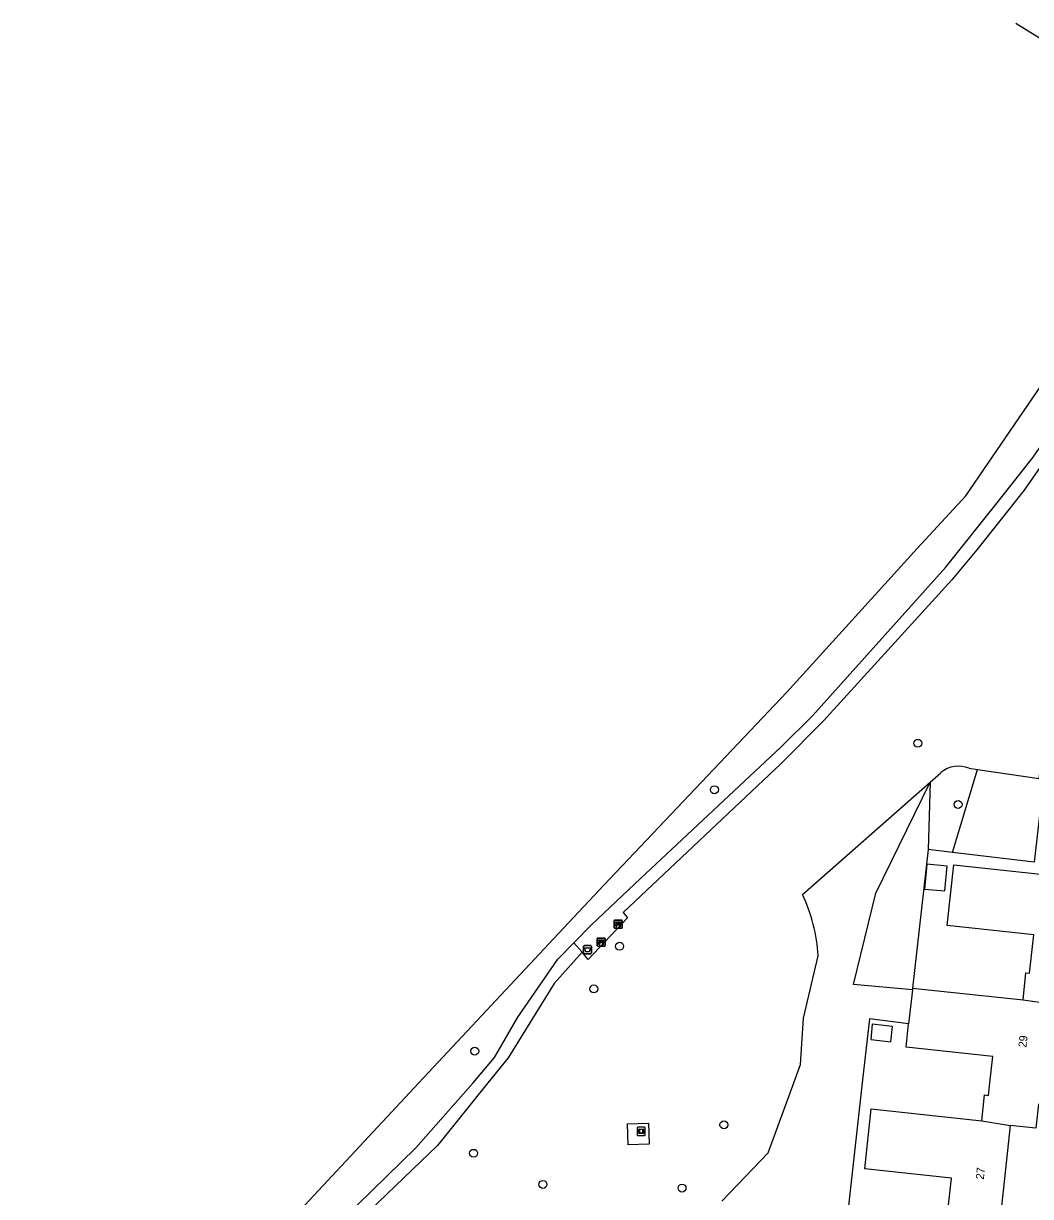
# Model space of a CAD drawing. Extents: x 162398 to 163643, y 386453 to 387397.
# Drawn here: x 162588.7 to 162713.1, y 386736 to 386880.9 of the extents above; entities that cross this region are included whole.
import ezdxf

# ---------------------------------------------------------------- set-up
doc = ezdxf.new("R2010")
doc.units = 0
for name, color, linetype in [('IMGEO_Afvalbak', 7, 'Continuous'), ('IMGEO_Bank', 7, 'Continuous'), ('IMGEO_Boom', 7, 'Continuous'), ('IMGEO_Groenvoorziening', 7, 'Continuous'), ('IMGEO_Kunstobject', 7, 'Continuous'), ('IMGEO_Meer_plas_ven_vijver', 7, 'Continuous'), ('IMGEO_Muur', 7, 'Continuous'), ('IMGEO_Pand', 7, 'Continuous'), ('IMGEO_Pand_nummerreeks', 7, 'Continuous'), ('IMGEO_Voetpad_gesloten', 7, 'Continuous')]:
    doc.layers.add(name, color=color, linetype=linetype)

msp = doc.modelspace()

# ---------------------------------------------------------------- linework, layer by layer
at = {"layer": 'IMGEO_Afvalbak'}
for p, q in [((162657.86, 386766.07), (162657.86, 386766.87)), ((162657.86, 386766.87), (162657.86, 386766.07)), ((162657.96, 386766.97), (162658.75, 386766.97)), ((162658.75, 386766.97), (162657.96, 386766.97)), ((162658.85, 386766.87), (162658.85, 386766.07)), ((162658.85, 386766.07), (162658.85, 386766.87)), ((162658.75, 386765.97), (162657.96, 386765.97)), ((162657.96, 386765.97), (162658.75, 386765.97))]:
    msp.add_line(p, q, dxfattribs=at)
msp.add_lwpolyline([(162658.01, 386766.69), (162658.71, 386766.69), (162658.56, 386766.22), (162658.16, 386766.22), (162658.01, 386766.69)], dxfattribs=at)
for centre, start, end in [((162657.96, 386766.87), 90, 180), ((162657.96, 386766.87), 90, 180), ((162658.75, 386766.87), 0, 90), ((162658.75, 386766.87), 360, 90), ((162657.96, 386766.07), 180, 270), ((162657.96, 386766.07), 180, 270), ((162658.75, 386766.07), 270, 0), ((162658.75, 386766.07), 270, 0)]:
    msp.add_arc(centre, 0.1, start, end, dxfattribs=at)
at = {"layer": 'IMGEO_Bank'}
for p, q in [((162661.65, 386769.2), (162661.65, 386770.04)), ((162661.65, 386770.04), (162661.65, 386769.2)), ((162661.72, 386770.12), (162662.56, 386770.12)), ((162662.56, 386770.12), (162661.72, 386770.12)), ((162662.34, 386769.52), (162661.95, 386769.52)), ((162661.96, 386769.63), (162661.96, 386769.74)), ((162662, 386769.74), (162662, 386769.63)), ((162662.29, 386769.74), (162662.01, 386769.74)), ((162662.01, 386769.62), (162662.29, 386769.62)), ((162662.3, 386769.63), (162662.3, 386769.74)), ((162662.34, 386769.74), (162662.34, 386769.63)), ((162662.65, 386770.05), (162662.65, 386769.21)), ((162662.65, 386769.21), (162662.65, 386770.05)), ((162659.6, 386767.91), (162660.44, 386767.91)), ((162660.44, 386767.91), (162659.6, 386767.91)), ((162662.57, 386769.13), (162661.73, 386769.13)), ((162661.73, 386769.13), (162662.57, 386769.13)), ((162659.53, 386766.98), (162659.53, 386767.83)), ((162659.53, 386767.83), (162659.53, 386766.98)), ((162660.45, 386766.91), (162659.61, 386766.91)), ((162659.61, 386766.91), (162660.45, 386766.91)), ((162660.22, 386767.31), (162659.83, 386767.31)), ((162659.84, 386767.42), (162659.84, 386767.52)), ((162659.88, 386767.52), (162659.88, 386767.42)), ((162660.17, 386767.53), (162659.89, 386767.53)), ((162659.89, 386767.41), (162660.17, 386767.41)), ((162660.17, 386767.42), (162660.17, 386767.52)), ((162660.22, 386767.52), (162660.22, 386767.42)), ((162660.53, 386767.84), (162660.53, 386766.99)), ((162660.53, 386766.99), (162660.53, 386767.84))]:
    msp.add_line(p, q, dxfattribs=at)
for points in [[(162661.9, 386769.52), (162661.75, 386769.52), (162661.86, 386769.62), (162661.95, 386769.62)], [(162661.95, 386769.74), (162661.86, 386769.74), (162661.86, 386769.9), (162662.43, 386769.9), (162662.43, 386769.74), (162662.35, 386769.74)], [(162661.95, 386769.52), (162661.95, 386769.31), (162661.9, 386769.31), (162661.9, 386769.52)], [(162662.35, 386769.62), (162662.43, 386769.62), (162662.54, 386769.52), (162662.4, 386769.52)], [(162662.39, 386769.52), (162662.39, 386769.31), (162662.35, 386769.31), (162662.35, 386769.52)], [(162659.77, 386767.31), (162659.63, 386767.31), (162659.74, 386767.41), (162659.83, 386767.41)], [(162659.83, 386767.53), (162659.74, 386767.53), (162659.74, 386767.69), (162660.31, 386767.69), (162660.31, 386767.53), (162660.22, 386767.53)], [(162659.82, 386767.3), (162659.82, 386767.09), (162659.78, 386767.09), (162659.78, 386767.3)], [(162660.22, 386767.41), (162660.31, 386767.41), (162660.42, 386767.31), (162660.28, 386767.31)], [(162660.27, 386767.3), (162660.27, 386767.09), (162660.23, 386767.09), (162660.23, 386767.3)]]:
    msp.add_lwpolyline(points, dxfattribs=at)
for centre, radius, start, end in [((162661.73, 386770.05), 0.0779, 92.4484, 184.2845), ((162661.73, 386770.05), 0.0779, 92.4484, 184.2845), ((162661.9, 386769.52), 0.00671, 2.8957, 87.1043), ((162661.95, 386769.74), 0.00671, 2.8957, 87.1043), ((162661.95, 386769.63), 0.00671, 272.8957, 357.1043), ((162661.95, 386769.52), 0.00671, 92.8957, 177.1043), ((162662.01, 386769.74), 0.00671, 92.8957, 177.1043), ((162662.01, 386769.63), 0.00671, 182.8957, 267.1043), ((162662.29, 386769.74), 0.00671, 2.8957, 87.1043), ((162662.29, 386769.63), 0.00671, 272.8957, 357.1043), ((162662.35, 386769.74), 0.00671, 92.8957, 177.1043), ((162662.35, 386769.63), 0.00671, 182.8957, 267.1043), ((162662.34, 386769.52), 0.00671, 2.8957, 87.1043), ((162662.4, 386769.52), 0.00671, 92.8957, 177.1043), ((162662.57, 386770.05), 0.0779, 2.4484, 94.2845), ((162662.57, 386770.05), 0.0779, 2.4484, 94.2845), ((162659.6, 386767.83), 0.0779, 92.4484, 184.2845), ((162659.6, 386767.83), 0.0779, 92.4484, 184.2845), ((162660.45, 386767.83), 0.0779, 2.4484, 94.2845), ((162660.45, 386767.83), 0.0779, 2.4484, 94.2845), ((162661.73, 386769.2), 0.0779, 182.4484, 274.2845), ((162661.73, 386769.2), 0.0779, 182.4484, 274.2845), ((162662.57, 386769.2), 0.0779, 272.4484, 4.2845), ((162662.57, 386769.2), 0.0779, 272.4484, 4.2845), ((162659.6, 386766.99), 0.0779, 182.4484, 274.2845), ((162659.6, 386766.99), 0.0779, 182.4484, 274.2845), ((162659.77, 386767.3), 0.00671, 2.8957, 87.1043), ((162659.83, 386767.3), 0.00671, 92.8957, 177.1043), ((162659.83, 386767.52), 0.00671, 2.8957, 87.1043), ((162659.83, 386767.42), 0.00671, 272.8957, 357.1043), ((162659.89, 386767.52), 0.00671, 92.8957, 177.1043), ((162659.89, 386767.42), 0.00671, 182.8957, 267.1043), ((162660.17, 386767.52), 0.00671, 2.8957, 87.1043), ((162660.17, 386767.42), 0.00671, 272.8957, 357.1043), ((162660.22, 386767.52), 0.00671, 92.8957, 177.1043), ((162660.22, 386767.42), 0.00671, 182.8957, 267.1043), ((162660.22, 386767.3), 0.00671, 2.8957, 87.1043), ((162660.28, 386767.3), 0.00671, 92.8957, 177.1043), ((162660.45, 386766.99), 0.0779, 272.4484, 4.2845), ((162660.45, 386766.99), 0.0779, 272.4484, 4.2845)]:
    msp.add_arc(centre, radius, start, end, dxfattribs=at)
at = {"layer": 'IMGEO_Boom'}
for centre in [(162699.17, 386791.98), (162674.03, 386786.24), (162704.14, 386784.42), (162662.32, 386766.9), (162659.13, 386761.62), (162644.42, 386753.93), (162675.21, 386744.83), (162644.27, 386741.31), (162652.84, 386737.46), (162670.03, 386737.01)]:
    msp.add_circle(centre, 0.489, dxfattribs=at)
at = {"layer": 'IMGEO_Groenvoorziening'}
for points in [[(162706.54, 386788.74), (162714.16, 386787.65), (162715.15, 386795.3), (162718.5, 386794.99), (162720.32, 386812.43)], [(162718.93, 386793.93), (162715.48, 386794.24), (162713.55, 386777.29), (162703.46, 386778.49)], [(162700.68, 386787.19), (162702, 386788.35)], [(162703.46, 386778.49), (162706.54, 386788.74)], [(162705.5, 386788.89), (162706.54, 386788.74)], [(162684.93, 386773.31), (162700.68, 386787.19)], [(162698.49, 386761.51), (162691.21, 386762.18), (162693.99, 386773.44), (162700.68, 386787.19)], [(162700.68, 386787.19), (162700.44, 386778.85)], [(162700.44, 386778.85), (162698.51, 386761.73)], [(162703.46, 386778.49), (162700.44, 386778.85)], [(162674.96, 386735.41), (162680.69, 386741.35), (162683.83, 386750), (162684.66, 386752.27), (162685.04, 386758.03), (162686.86, 386765.7)], [(162698.03, 386757.32), (162693.19, 386757.94), (162692.3, 386750), (162690.13, 386730.75)]]:
    msp.add_lwpolyline(points, dxfattribs=at)
for centre, radius, start, end in [((162704.2, 386785.71), 3.44, 67.7169, 129.7632), ((162665.9, 386764.41), 21, 3.5108, 25.0642)]:
    msp.add_arc(centre, radius, start, end, dxfattribs=at)
at = {"layer": 'IMGEO_Kunstobject'}
for p, q in [((162664.48, 386744.44), (162664.48, 386743.6)), ((162664.48, 386744.44), (162664.48, 386743.6)), ((162665.39, 386744.52), (162664.55, 386744.52)), ((162665.39, 386744.52), (162664.55, 386744.52)), ((162664.56, 386743.52), (162665.4, 386743.52)), ((162664.56, 386743.52), (162665.4, 386743.52)), ((162664.69, 386743.79), (162664.69, 386744.26)), ((162664.74, 386744.31), (162665.22, 386744.31)), ((162665.22, 386743.74), (162664.74, 386743.74)), ((162664.77, 386744.21), (162664.77, 386743.84)), ((162665.17, 386744.23), (162664.79, 386744.23)), ((162664.79, 386743.82), (162665.17, 386743.82)), ((162665.19, 386743.84), (162665.19, 386744.21)), ((162665.27, 386744.26), (162665.27, 386743.79)), ((162665.48, 386743.61), (162665.48, 386744.45)), ((162665.48, 386743.61), (162665.48, 386744.45))]:
    msp.add_line(p, q, dxfattribs=at)
for centre, radius, start, end in [((162664.56, 386744.44), 0.0779, 92.4484, 184.2845), ((162664.56, 386744.44), 0.0779, 92.4484, 184.2845), ((162664.56, 386743.6), 0.0779, 182.4484, 274.2845), ((162664.56, 386743.6), 0.0779, 182.4484, 274.2845), ((162664.74, 386744.26), 0.05, 90, 180), ((162664.74, 386743.79), 0.05, 180, 270), ((162664.79, 386744.21), 0.02, 90, 180), ((162664.79, 386743.84), 0.02, 180, 270), ((162665.17, 386744.21), 0.02, 360, 90), ((162665.17, 386743.84), 0.02, 270, 0), ((162665.22, 386744.26), 0.05, 360, 90), ((162665.22, 386743.79), 0.05, 270, 0), ((162665.4, 386744.44), 0.0779, 2.4484, 94.2845), ((162665.4, 386744.44), 0.0779, 2.4484, 94.2845), ((162665.4, 386743.6), 0.0779, 272.4484, 4.2845), ((162665.4, 386743.6), 0.0779, 272.4484, 4.2845)]:
    msp.add_arc(centre, radius, start, end, dxfattribs=at)
at = {"layer": 'IMGEO_Meer_plas_ven_vijver'}
for points in [[(162730.49, 386868.98), (162711.27, 386880.94)], [(162623.43, 386734.89), (162637.52, 386750), (162654.77, 386768.49), (162660.37, 386774.43), (162682.99, 386798.29), (162699.09, 386816.07), (162705.11, 386822.55), (162731.99, 386861.89)]]:
    msp.add_lwpolyline(points, dxfattribs=at)
at = {"layer": 'IMGEO_Muur'}
msp.add_lwpolyline([(162665.88, 386745.02), (162665.96, 386742.42), (162663.37, 386742.34), (162663.29, 386744.94), (162665.88, 386745.02)], dxfattribs=at)
at = {"layer": 'IMGEO_Pand'}
for points in [[(162700.26, 386777.03), (162699.99, 386773.97), (162702.51, 386773.75), (162702.78, 386776.81), (162700.26, 386777.03)], [(162712.17, 386760.26), (162712.53, 386763.61), (162712.96, 386763.56), (162713.48, 386768.3), (162702.81, 386769.46), (162703.62, 386776.94), (162720.81, 386775.09), (162719.45, 386762.48), (162719.21, 386762.51), (162718.88, 386759.43), (162715.69, 386759.78)], [(162698.49, 386761.51), (162698.03, 386757.32)], [(162698.51, 386761.73), (162698.49, 386761.51)], [(162698.51, 386761.73), (162712.17, 386760.26)], [(162715.69, 386759.78), (162714.64, 386750), (162714.35, 386747.36), (162714.08, 386747.39), (162713.76, 386744.41), (162710.57, 386744.75)], [(162712.17, 386760.26), (162715.69, 386759.78)], [(162693.34, 386755.37), (162695.81, 386755.1), (162696.02, 386756.99), (162693.54, 386757.26), (162693.34, 386755.37)], [(162707.06, 386745.31), (162707.41, 386748.52), (162707.9, 386748.47), (162708.07, 386750), (162708.42, 386753.26), (162697.72, 386754.42), (162698.03, 386757.32)], [(162700.65, 386726.43), (162701.42, 386733.57), (162702.8, 386733.42), (162703.31, 386738.22), (162692.61, 386739.37), (162693.42, 386746.79), (162707.06, 386745.31)], [(162707.06, 386745.31), (162710.57, 386744.75)], [(162710.57, 386744.75), (162709.24, 386732.42), (162708.99, 386732.44), (162708.25, 386725.6)]]:
    msp.add_lwpolyline(points, dxfattribs=at)
at = {"layer": 'IMGEO_Voetpad_gesloten'}
for points in [[(162656.68, 386767.33), (162658.88, 386769.57), (162664.9, 386775.28), (162682.25, 386791.5), (162686.15, 386795.37), (162702.58, 386813.7), (162708.98, 386821.68), (162713.41, 386827.33), (162729.89, 386851.16)], [(162717.91, 386831.34), (162712.29, 386823.28), (162706.46, 386815.91), (162703.35, 386812.19), (162701.77, 386810.4), (162687.52, 386794.75), (162682.22, 386789.46), (162662.74, 386771.05), (162663.31, 386770.43), (162658.45, 386765.26), (162657.71, 386766.15)], [(162608.31, 386714.96), (162614.38, 386721.24), (162621.61, 386728.11), (162628.11, 386733.18), (162637.12, 386741.98), (162644.23, 386750), (162646.86, 386753.13), (162649.73, 386758.14), (162654.67, 386765.29), (162656.68, 386767.33)], [(162657.71, 386766.15), (162656.68, 386767.33)], [(162657.71, 386766.15), (162654.23, 386762.29), (162648.53, 386753.09), (162646.04, 386750), (162639.8, 386742.28), (162630.43, 386733.24), (162623.41, 386727.72), (162621.19, 386725.66), (162604.67, 386709.54), (162603.24, 386707.75), (162588.66, 386686.74)]]:
    msp.add_lwpolyline(points, dxfattribs=at)

# ---------------------------------------------------------------- texts
at = {"layer": 'IMGEO_Pand_nummerreeks'}
for s, rotation, p in [('29', 83.8361, (162712.57, 386754.34)), ('27', 83.8373, (162707.31, 386738.03))]:
    msp.add_text(s, height=1, rotation=rotation, dxfattribs=at).set_placement(p)

doc.saveas('drawing.dxf')
